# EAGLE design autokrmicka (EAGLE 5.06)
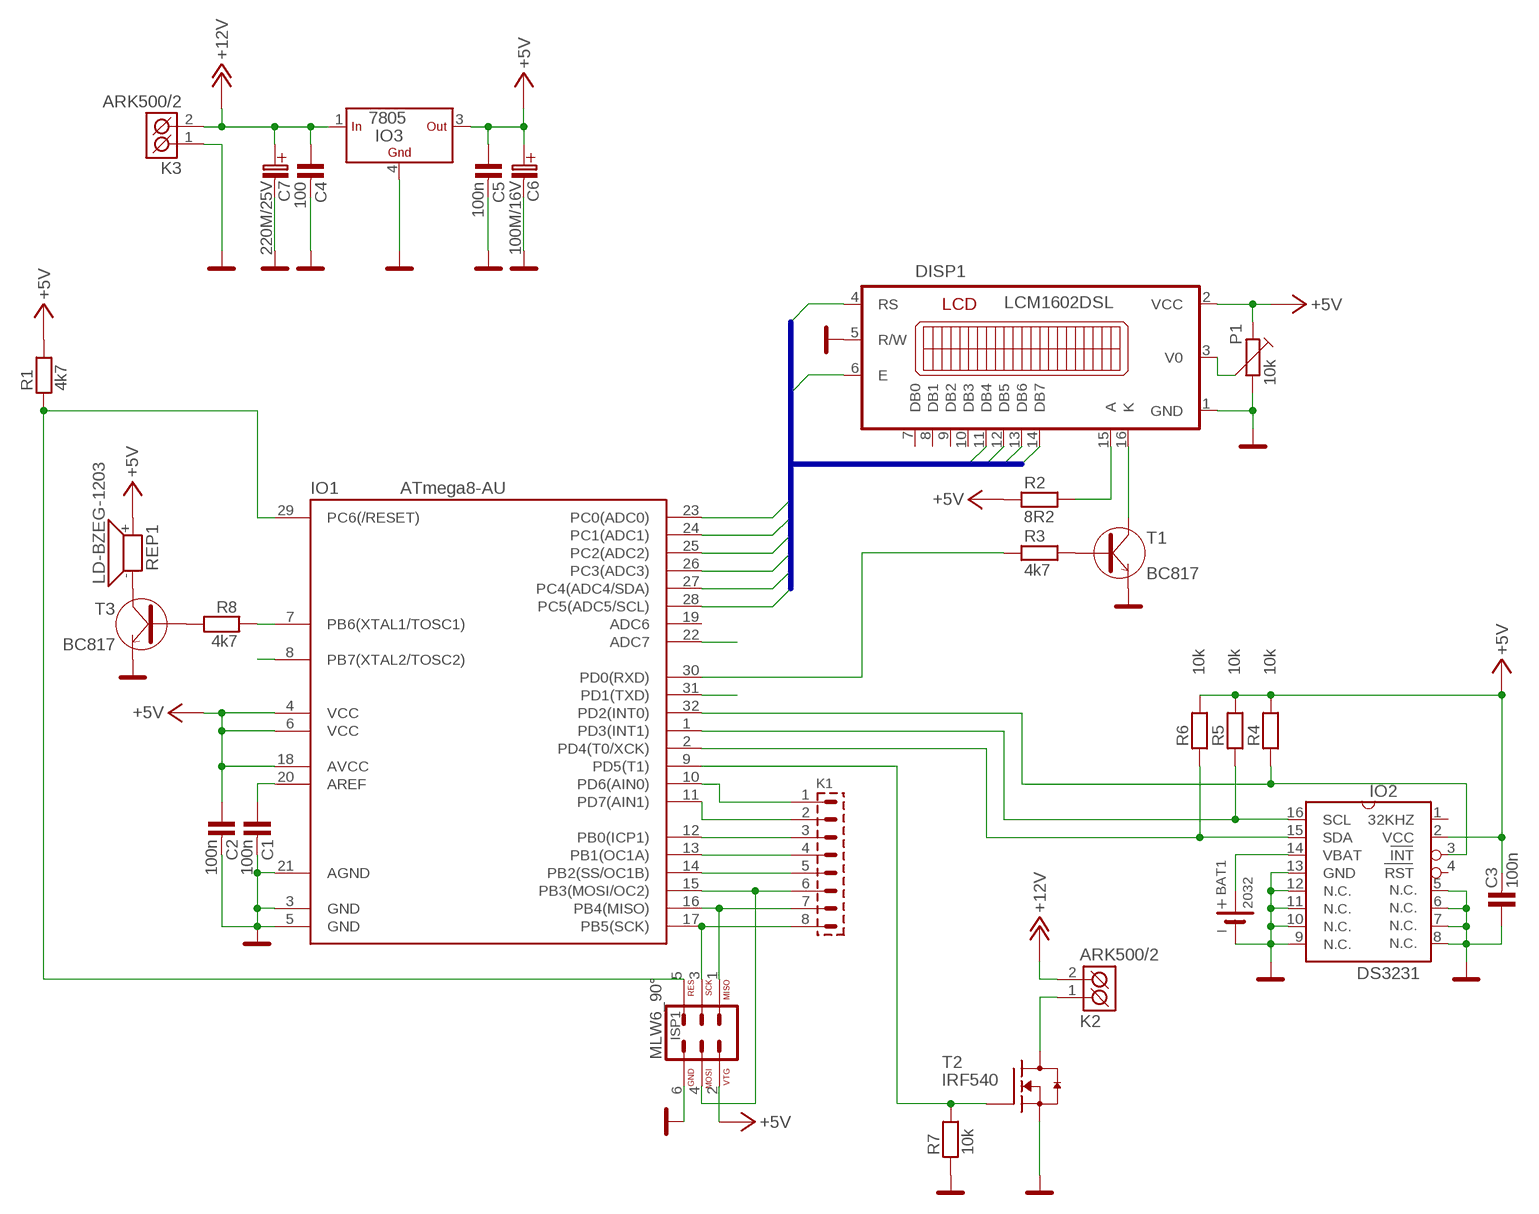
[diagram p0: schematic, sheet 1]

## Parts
BAT1  2032  [SN2032]
C1  100n  C-KER_0805  [0805]
C2  100n  C-KER_0805  [0805]
C3  100n  C-KER_1206  [1206]
C4  100  C-KER_1206  [1206]
C5  100n  C-KER_1206  [1206]
C6  100M/16V  100M/16V_SMD  [C_EL-SMD_D]
C7  220M/25V  [C_EL_3,5]
DISP1  LCM1602DSL  [LCM1602DSL]
IO1  ATmega8-AU  MEGA8_-AU  [TQFP32-08]
IO2  DS3231  [SO16L]
IO3  7805  78_D2T  [D2PAK]
ISP1  MLW6_90°  AVR_ISP_90°  [MLW06A]
K1  PSH02-08W  [PSH02-08W]
K2  ARK500/2  [ARK500/2]
K3  ARK500/2  [ARK500/2]
P1  10k  TRIMRPT6VSMD  [PT6VSMD]
R1  4k7  R_1206  [1206]
R2  8R2  R_1206  [1206]
R3  4k7  R_1206  [1206]
R4  10k  R_1206  [1206]
R5  10k  R_1206  [1206]
R6  10k  R_1206  [1206]
R7  10k  R_1206  [1206]
R8  4k7  R_1206  [1206]
REP1  LD-BZEG-1203  SIR_0905  [LD-BZEG-0905]
T1  BC817  [SOT-23]
T2  IRF540  IRF840  [TO220AV]
T3  BC817  [SOT-23]

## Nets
+5V: C2.1 C3.2 C5.1 C6.+(C_EL+) DISP1.2(VCC) IO1.4(VCC) IO1.6(VCC) IO1.18(AVCC) IO2.2(VCC) IO3.3(OUT) ISP1.2 P1.1 R1.2 R2.1 R4.2 R5.2 R6.2 REP1.+
+12V: C4.1 C7.C+(C_EL+) IO3.1(IN) K2.2(K2) K3.2(K2)
+BAT: BAT1.+ IO2.14(VBAT)
ADC7: IO1.22(ADC7)
DB4: DISP1.11(DB4) IO1.25(PC2(ADC2))
DB5: DISP1.12(DB5) IO1.26(PC3(ADC3))
DB6: DISP1.13(DB6) IO1.27(PC4(ADC4/SDA))
DB7: DISP1.14(DB7) IO1.28(PC5(ADC5/SCL))
E: DISP1.6(E) IO1.24(PC1(ADC1))
GND: BAT1.- C1.2 C2.2 C3.1 C4.2 C5.2 C6.-(C_EL-) C7.C-(C_EL-) DISP1.1(GND) DISP1.5(R/W) IO1.3(GND) IO1.5(GND) IO1.21(AGND) IO2.5 IO2.6 IO2.7 IO2.8 IO2.9 IO2.10 IO2.11 IO2.12 IO2.13(GND) IO3.4(GND) ISP1.6 K3.1(K1) P1.2 R7.1 T1.2(E) T2.3(S) T3.2(E)
N$1: IO1.16(PB4(MISO)) ISP1.1 K1.7
N$2: IO1.17(PB5(SCK)) ISP1.3 K1.8
N$3: IO1.15(PB3(MOSI/OC2)) ISP1.4 K1.6
N$4: IO1.29(PC6(/RESET)) ISP1.5 R1.1
N$5: DISP1.15(A) R2.2
N$6: C1.1 IO1.20(AREF)
N$7: DISP1.16(K) T1.3(C)
N$8: R3.2 T1.1(B)
N$9: DISP1.3(V0) P1.3
N$10: IO1.14(PB2(SS/OC1B)) K1.5
N$11: IO1.13(PB1(OC1A)) K1.4
N$12: IO1.12(PB0(ICP1)) K1.3
N$13: IO1.11(PD7(AIN1)) K1.2
N$14: IO1.10(PD6(AIN0)) K1.1
N$15: K2.1(K1) T2.2(D)
N$16: IO1.9(PD5(T1)) R7.2 T2.1(G)
N$17: IO1.30(PD0(RXD)) R3.1
N$18: IO1.32(PD2(INT0)) IO2.3(INT) R4.1
N$19: IO1.1(PD3(INT1)) IO2.16(SCL) R5.1
N$20: IO1.2(PD4(T0/XCK)) IO2.15(SDA) R6.1
N$21: R8.2 T3.1(B)
N$22: REP1.- T3.3(C)
N$23: IO1.7(PB6(XTAL1/TOSC1)) R8.1
PB7: IO1.8(PB7(XTAL2/TOSC2))
PD1: IO1.31(PD1(TXD))
RS: DISP1.4(RS) IO1.23(PC0(ADC0))
Unconnected: DISP1.7(DB0) DISP1.8(DB1) DISP1.9(DB2) DISP1.10(DB3) IO1.19(ADC6) IO2.1(32KHZ) IO2.4(RST)

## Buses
LCD

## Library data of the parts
BAT1 = #PaJa_32:2032: Battery 2032
C1-C5 = #PaJa_32:C-KER: Kondenzator - keramicky
C6 = #PaJa_C-el_2:100M/16V
C7 = #PaJa_C-el_2:220M/25V
DISP1 = #PaJa_displeje:LCM1602DSL: LCD - 2x16 + LED (TME - LCM1602DSL)
IO1 = avr-7:MEGA8_
IO2 = #PaJa_32:DS3231: RTC
IO3 = #PaJa_32:78?: Stabilizator - 1A a 1,5A ? - napeti => 05, 06, 08, 09, 12, 15, 18, 20, 24 => 1,5A ? - napeti => 10, 12, 15, 18 => 1A S ? - napeti => 05, 09, 10, 12, 15, 18, 24 => 2A T ? - napeti => 05 => 3A ------------------------------------------------------- Stabilizator - 100mA (TO-92 , SOT-89) ? - napeti =>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
ISP1 = #PaJa_32:AVR_ISP: AVR ISP konektor (dle standardu)
K1 = #PaJa_konektory:PSH02-08: Konektory se zamkem - vidlice - 8pin
K2 K3 = #PaJa_konektory:ARK500/2: Svorkovnice - roztec 5mm - dvojita
P1 = #PaJa_32:TRIMR: Trimr
R1-R8 = #PaJa_32:R: Rezistor
REP1 = #PaJa_32:SIR: Piezo-sirenka - 70dB - 3V az 16V
T1 T3 = #PaJa_32:BC817: SMD tranzistor - NPN - ekv. BC337
T2 = Jan16:IRF840

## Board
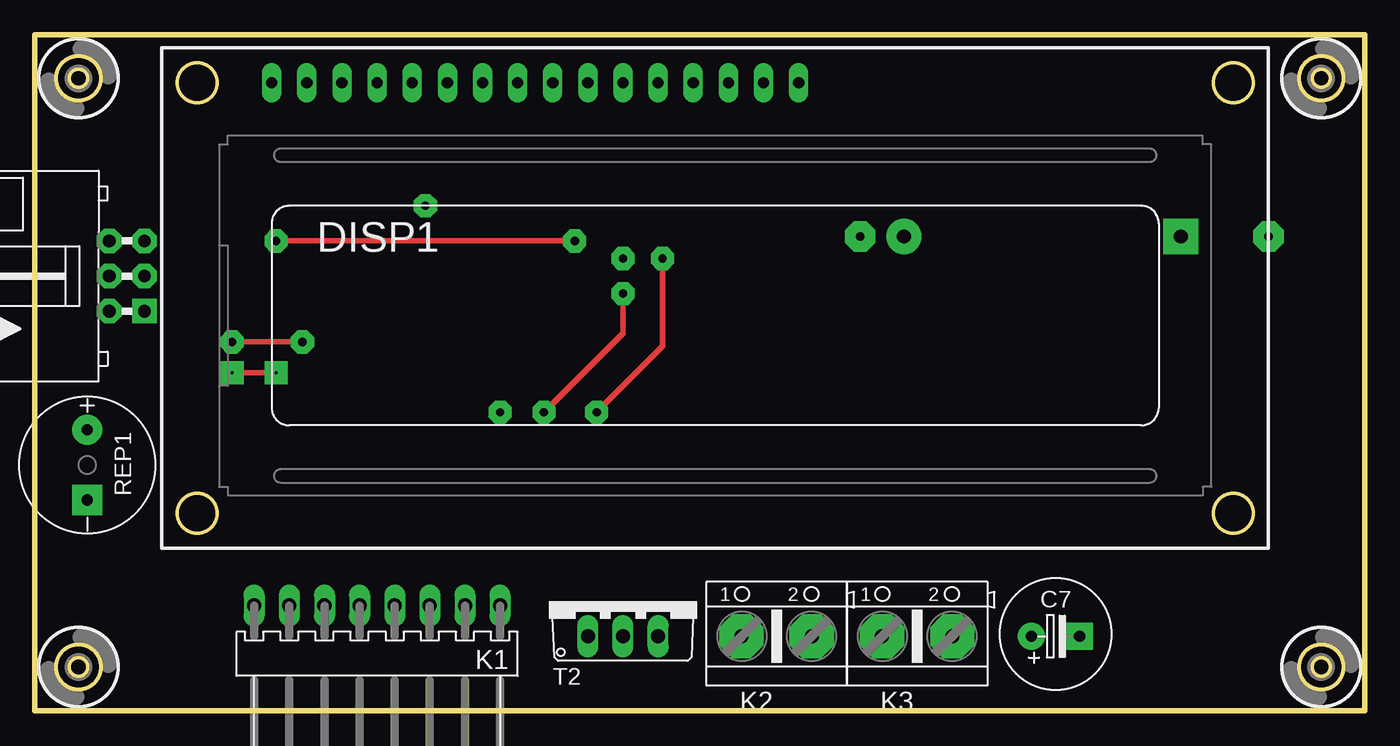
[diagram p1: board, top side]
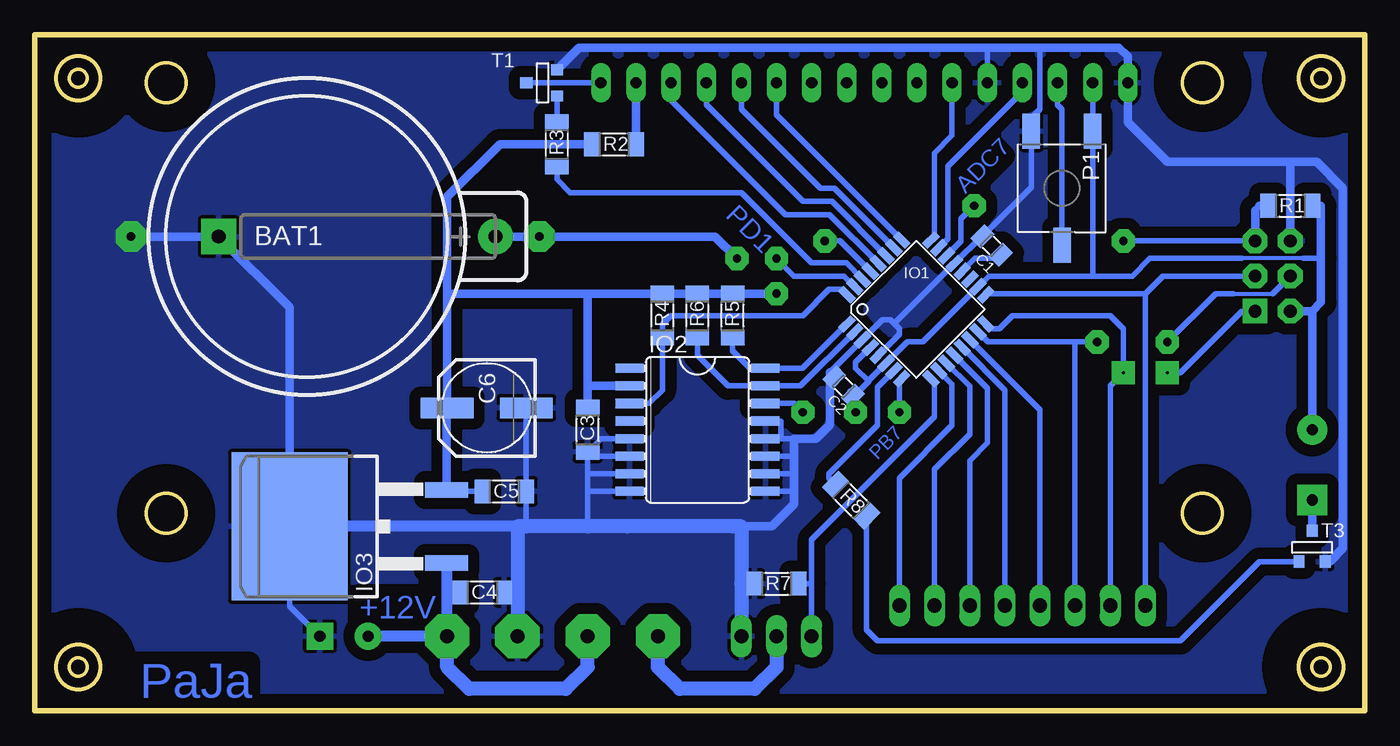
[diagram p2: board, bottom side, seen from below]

Size 96.19 x 48.88 mm. Coordinates in mm from the lower left corner, seen from the top.
Outline: 0,0 96.19,0 96.19,48.88 0,48.88 0,0
Copper layers (1*16): Top 0.035mm / dielectric 1.5mm / Bottom 0.035mm
Design rules "default": minimum track width 10mil, minimum drill 24mil, track to track 8mil, track to pad 8mil, pad to pad 8mil, via to via 8mil, smd to smd 8mil, copper to edge 40mil, drill to drill 8mil, minimum pad ring 10mil, minimum via ring 8mil, stop-mask expansion 4mil, vias tented up to drill 0mil, thermal gap 10mil

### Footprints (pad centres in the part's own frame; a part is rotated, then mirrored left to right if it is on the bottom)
SN2032 = drill 1 pad 2.54 round: + 13.652,0 | drill 1 pad 2.54 square: - -6.35,0
0805 = smd 1.016 x 1.422: 1 -0.953,0; 2 0.953,0
1206 = smd 1.143 x 1.702: 1 -1.587,0; 2 1.587,0
C_EL-SMD_D = smd 3.81 x 1.473: + 2.857,0; - -2.857,0
C_EL_3,5 = drill 0.813 pad 1.93 round: C+ 0,0 | drill 0.813 pad 1.93 square: C- 3.493,0
LCM1602DSL = drill 0.813 pad 1.422 long: 1 -32.068,16.828; 2 -29.527,16.828; 3 -26.988,16.828; 4 -24.448,16.828; 5 -21.907,16.828; 6 -19.367,16.828; 7 -16.828,16.828; 8 -14.287,16.828; 9 -11.748,16.828; 10 -9.207,16.828; 11 -6.668,16.828; 12 -4.128,16.828; 13 -1.587,16.828; 14 0.953,16.828; 15 3.493,16.828; 16 6.032,16.828 | hole 2.8: -37.465,-14.287; 37.465,-14.287; 37.465,16.828; -37.465,16.828
TQFP32-08 = smd 1.27 x 0.559: 1 -4.293,2.8; 2 -4.293,2; 3 -4.293,1.2; 4 -4.293,0.4; 5 -4.293,-0.4; 6 -4.293,-1.2; 7 -4.293,-2; 8 -4.293,-2.8; 17 4.293,-2.8; 18 4.293,-2; 19 4.293,-1.2; 20 4.293,-0.4; 21 4.293,0.4; 22 4.293,1.2; 23 4.293,2; 24 4.293,2.8 | smd 0.559 x 1.27: 9 -2.8,-4.293; 10 -2,-4.293; 11 -1.2,-4.293; 12 -0.4,-4.293; 13 0.4,-4.293; 14 1.2,-4.293; 15 2,-4.293; 16 2.8,-4.293; 25 2.8,4.293; 26 2,4.293; 27 1.2,4.293; 28 0.4,4.293; 29 -0.4,4.293; 30 -1.2,4.293; 31 -2,4.293; 32 -2.8,4.293
SO16L = smd 0.66 x 2.032: 1 -4.445,-4.902; 2 -3.175,-4.902; 3 -1.905,-4.902; 4 -0.635,-4.902; 5 0.635,-4.902; 6 1.905,-4.902; 7 3.175,-4.902; 8 4.445,-4.902; 9 4.445,4.902; 10 3.175,4.902; 11 1.905,4.902; 12 0.635,4.902; 13 -0.635,4.902; 14 -1.905,4.902; 15 -3.175,4.902; 16 -4.445,4.902
D2PAK = smd 1.1 x 3.1: 1 -2.641,-8.535; 3 2.641,-8.535 | smd 10.7 x 8.4: 4 0,2.817
MLW06A = drill 0.914 pad 1.778 square: 1 -2.54,-1.27 | drill 0.914 pad 1.778 octagon: 2 -2.54,1.27; 3 0,-1.27; 4 0,1.27; 5 2.54,-1.27; 6 2.54,1.27
PSH02-08W = drill 1.016 pad 1.422 long: 1 -8.89,0; 2 -6.35,0; 3 -3.81,0; 4 -1.27,0; 5 1.27,0; 6 3.81,0; 7 6.35,0; 8 8.89,0
ARK500/2 = drill 1 pad 3.2 octagon: 1 -2.54,0; 2 2.54,0
PT6VSMD = smd 1.27 x 2.54: 1 -2.223,-4.128; 2 2.223,-4.128; 3 0,4.128
LD-BZEG-0905 = drill 0.813 pad 2.184 round: + -2.54,0 | drill 0.813 pad 2.184 square: - 2.54,0
SOT-23 = smd 0.787 x 0.889: 1 -0.953,-0.953; 2 0.953,-0.953; 3 0,1.27
TO220AV = drill 1.016 long: 1 -2.54,0; 2 0,0; 3 2.54,0
HOLE_3,0 = hole 3.2: 0,0

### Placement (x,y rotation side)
BAT1  76.52,34.29 0 bottom
C1  27,33.65 135 bottom
C2  37.7,23.45 135 bottom
C3  56.2,20.32 90 bottom
C4  63.82,8.57 0 bottom
C5  62.23,15.88 0 bottom
C6  63.5,21.91 180 bottom
C7  72.07,5.4 0 top
DISP1  49.21,28.57 0 top
IO1  32.44,29.02 45 bottom
IO2  48.26,20.32 270 bottom
IO3  74.93,13.34 90 bottom
ISP1  6.67,31.43 90 top
K1  24.77,7.62 180 top
K2  53.66,5.4 0 top
K3  63.82,5.4 0 top
P1  21.91,37.78 180 bottom
R1  5.4,36.51 0 bottom
R2  54.29,40.96 0 bottom
R3  58.42,40.96 90 bottom
R4  50.8,28.57 90 bottom
R5  45.72,28.57 90 bottom
R6  48.26,28.57 90 bottom
R7  42.55,9.21 0 bottom
R8  37.15,15.24 315 bottom
REP1  3.81,17.78 270 top
T1  59.37,45.4 90 bottom
T2  42.55,5.4 0 top
T3  3.81,11.75 0 bottom
U$1  [HOLE_3,0]  3.17,3.17 0 top
U$2  [HOLE_3,0]  93.03,3.17 0 top
U$3  [HOLE_3,0]  93.03,45.72 0 top
U$4  [HOLE_3,0]  3.17,45.72 0 top

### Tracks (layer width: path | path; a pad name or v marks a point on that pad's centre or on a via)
+5V  (via drill 0.6 pad 1.68)
  Top 0.406: v36.83,21.59 42.55,27.3 v42.55,30.16
  Bottom 0.305: 4.45,32.7 8.89,32.7
  Bottom 0.406: DISP1.2 P1.1 19.68,31.43 | 19.68,31.43 27.2,31.43 IO1.18 31.96,26.67 33.1,26.67 IO1.6 35.88,23.89 35.88,23.81 | IO1.4 36.83,25.2 36.83,24.77 35.88,23.81 | C2.1 37.23,23.09 | 35.88,23.81 36.91,22.78 C2.1 | C6.+ 66.39,21.91 | C5.1 66.39,15.88 IO3.3 | 19.68,31.43 16.83,31.43 15.56,32.7 8.89,32.7 | 3.17,32.7 4.45,32.7 | v36.83,21.59 36.83,22.27 C2.1
  Bottom 0.61: 56.2,23.5 IO2.2 | 66.39,21.91 IO3.3 | 56.2,23.5 C3.2 | R2.1 62.55,40.96 66.36,37.15 66.36,30.16 | 66.36,30.16 C6.+ | 56.2,30.16 R4.2 R6.2 R5.2 v42.55,30.16 | 56.2,30.16 56.2,23.5 | 56.2,30.16 66.36,30.16 | R1.2 3.17,36.51 3.17,32.7 3.17,29.53 3.81,28.89 | 3.81,28.89 ISP1.2 | REP1.+ 3.81,28.89
+12V
  Bottom 0.406: 66.36,10.66 IO3.1 | 66.36,8.57 C4.1
  Bottom 0.813: 66.36,10.66 66.36,8.57 K3.2 C7.C+
  Bottom 1.016: K2.2 56.2,3.17 57.78,1.59 64.77,1.59 66.36,3.17 K3.2
+BAT  (via drill 0.6 pad 1.68, 0.6 pad 2.18)
  Top 0.406: v40.64,21.59 45.4,26.35 v45.4,32.7
  Bottom 0.406: IO2.14 41.27,22.23 v40.64,21.59
  Bottom 0.61: v45.4,32.7 46.99,34.29 v59.69,34.29 BAT1.+
ADC7  (via drill 0.6 pad 1.68)
  Bottom 0.406: IO1.22 29.21,33.95 29.21,35.56 v28.26,36.51
DB4
  Bottom 0.406: IO1.25 42.55,43.09 DISP1.11
DB5
  Bottom 0.406: IO1.26 38.37,37.78 39.37,37.78 45.09,43.5 DISP1.12
DB6
  Bottom 0.406: DISP1.13 47.62,43.81 40.64,36.83 38.55,36.83 IO1.27
DB7
  Bottom 0.406: DISP1.14 50.16,44.13 41.91,35.88 38.73,35.88 IO1.28
E
  Bottom 0.406: IO1.24 31.11,34.31 31.11,40.32 29.84,41.59 DISP1.6
GND  (via drill 0.6 pad 2.18)
  Bottom 0.406: 61.28,8.57 C4.2 | C7.C- 77.75,7.58 IO3.4 | 23.5,47.94 23.5,43.5 24.13,42.86 P1.2 24.13,37.86 C1.2 27.71,34.32 IO1.21 33.97,28.06 33.97,27.94 | 33.97,27.94 33.66,27.62 33.66,27.24 IO1.5 | 33.97,27.94 34.29,28.26 34.9,28.26 IO1.3 38.69,24.47 C2.2 | 56.2,15.88 IO2.8 | 56.2,15.88 56.2,17.14 | 56.2,17.14 C3.1 | IO2.5 55.24,19.68 C3.1 | IO2.6 55.88,18.41 C3.1 | 56.2,17.14 IO2.7 | IO2.12 41.27,19.68 42.23,19.68 42.23,20.95 IO2.13 | 41.27,18.41 IO2.11 | 41.27,17.14 IO2.10 | 41.27,15.88 IO2.9 | 56.2,13.34 56.2,15.88 | 60.64,13.34 C5.2 C6.- | 27.3,47.94 DISP1.5 | 2.54,10.79 T3.2 | 45.09,9.21 R7.1
  Bottom 0.61: 38.69,24.47 38.69,20.68 39.69,19.68 41.27,19.68 41.27,18.41 41.27,17.14 41.27,15.88 41.27,14.92 42.86,13.34 45.09,13.34 | T1.2 56.83,47.94 27.3,47.94 23.5,47.94 17.78,47.94 17.14,47.31 DISP1.1 17.14,42.55 14.29,39.69 5.4,39.69 | IO3.4 77.75,29.17 BAT1.- v89.22,34.29 | 5.4,39.69 ISP1.6 | 5.4,39.69 3.49,39.69 1.59,37.78 1.59,11.75 2.54,10.79
  Bottom 0.813: 61.28,13.34 IO3.4
  Bottom 1.016: K3.1 61.28,8.57 61.28,13.34 60.64,13.34 53.34,13.34 | 53.34,13.34 45.72,13.34 45.09,13.34 45.09,9.21 T2.3 | 53.34,13.34 56.2,13.34
  pour Bottom (isolate 0.813): 0,0 0,48.9 96.2,48.9 96.2,0
N$1  (via drill 0.2 pad 1.68)
  Top 0.406: v17.46,24.45 v14.29,24.45
  Bottom 0.406: IO1.16 27.33,27.97 26.99,27.62 26.44,27.62 25.49,28.57 18.41,28.57 17.46,27.62 v17.46,24.45 18.41,23.5 K1.7 | ISP1.1 8.89,28.89 13.34,24.45 v14.29,24.45
N$2
  Bottom 0.406: ISP1.3 14.61,31.43 15.88,30.16 | K1.8 15.88,30.16 | 15.88,30.16 27.34,30.16 IO1.17
N$3  (via drill 0.6 pad 1.68)
  Top 0.406: v19.37,26.67 v14.29,26.67
  Bottom 0.305: 9.53,30.16 6.67,30.16
  Bottom 0.406: 6.67,30.16 ISP1.4 | 20.95,26.67 v19.37,26.67 | 20.95,26.67 27.26,26.67 IO1.15 | K1.6 20.95,26.67 | v14.29,26.67 10.79,30.16 9.53,30.16
N$4  (via drill 0.6 pad 1.68)
  Top 0.406: v17.46,33.97 v39.05,33.97
  Bottom 0.406: IO1.29 37.95,33.97 v39.05,33.97 | ISP1.5 v17.46,33.97 | 7.62,36.51 7.94,36.2
  Bottom 0.61: R1.1 7.62,36.51 | 7.94,36.2 ISP1.5
N$5
  Bottom 0.61: R2.2 DISP1.15
N$6
  Bottom 0.406: IO1.20 28.2,32.7 26.99,32.7 26.72,32.97 C1.1
N$7
  Bottom 0.406: DISP1.16 T1.3
N$8
  Bottom 0.406: R3.2 T1.1
N$9
  Bottom 0.406: P1.3 21.91,43.5 22.23,43.81 DISP1.3
N$10
  Bottom 0.406: IO1.14 23.5,21.78 K1.5
N$11
  Bottom 0.406: IO1.13 26.04,23.18 K1.4
N$12
  Bottom 0.406: IO1.12 27.3,23.32 27.3,19.37 28.57,18.1 K1.3
N$13
  Bottom 0.406: IO1.11 28.57,23.46 28.57,20 31.11,17.46 K1.2
N$14
  Bottom 0.406: IO1.10 29.84,23.6 29.84,20.64 33.66,16.83 K1.1
N$15
  Bottom 1.016: T2.2 42.55,3.17 44.13,1.59 49.53,1.59 51.12,3.17 K2.1
N$16
  Bottom 0.406: IO1.9 31.11,23.74 31.11,21.27 40.01,12.38 40.01,9.21 | T2.1 40.01,9.21 | 40.01,9.21 R7.2
N$17
  Bottom 0.406: IO1.30 37.5,32.38 40.01,32.38 45.09,37.47 57.47,37.47 58.42,38.42 R3.1
N$18
  Bottom 0.406: IO2.3 51.75,22.23 50.8,23.18 R4.1 50.8,27.94 50.16,28.57 40.64,28.57 38.73,30.48 37.85,30.48 IO1.32
N$19
  Bottom 0.406: IO1.1 40.66,24.77 IO2.16 44.45,24.77 45.72,26.04 R5.1
N$20
  Bottom 0.406: IO1.2 40.8,23.5 IO2.15 46.04,23.5 48.26,25.72 R6.1
N$21
  Bottom 0.406: R8.2 36.02,5.86 35.24,5.08 13.34,5.08 7.62,10.79 T3.1
N$22
  Bottom 0.61: T3.3 REP1.-
N$23
  Bottom 0.406: IO1.7 35.24,23.39 35.24,20.64 38.73,17.14 38.73,16.83 R8.1 38.27,16.66
N$24  (via drill 0.6 pad 1.78)
  other vias: 11.75,14.29
N$25  (via drill 0.6 pad 1.78)
  other vias: 11.75,45.4
N$26  (via drill 0.6 pad 1.78)
  other vias: 86.68,45.4
N$27  (via drill 0.6 pad 1.78)
  other vias: 86.68,14.29
PB7  (via drill 0.6 pad 1.68)
  Bottom 0.406: IO1.8 33.66,23.85 v33.66,21.59
PD1  (via drill 0.6 pad 1.68)
  Bottom 0.406: IO1.31 37.68,31.43 41.27,31.43 v42.55,32.7
RS
  Bottom 0.406: DISP1.4 24.77,44.77 30.16,39.37 30.16,34.13 IO1.23

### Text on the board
Bottom: ADC7 | PD1 | PB7 | +12V | PaJa
PaJa: www.paja-trb.cz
